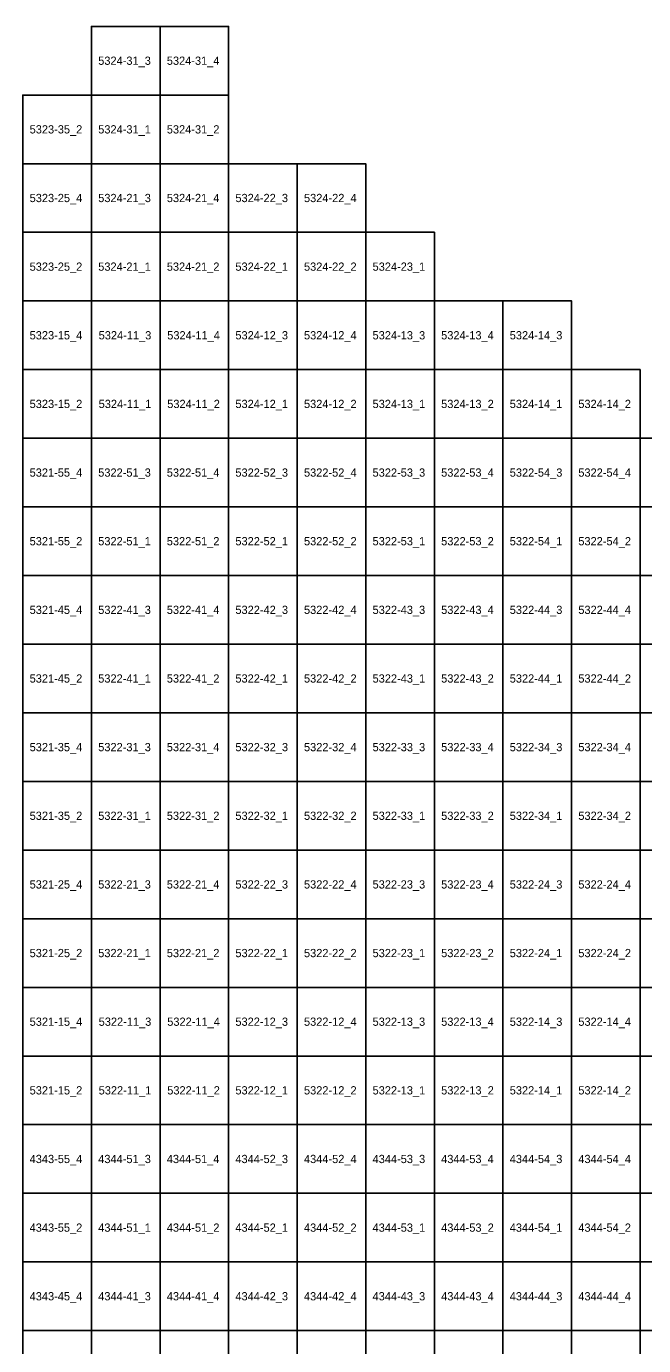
# Model space of a CAD drawing. Extents: x 312500 to 765000, y 172500 to 440000.
# Drawn here: x 572629 to 595129, y 391952 to 440000 of the extents above; entities that cross this region are included whole.
import ezdxf

# ---------------------------------------------------------------- set-up
doc = ezdxf.new("R2010")
doc.units = 0
doc.layers.add('Topo5_ramis_TKS2025', color=7, linetype='Continuous')
doc.layers.add('Topo5_ramis_TKS2025_Nr', color=7, linetype='Continuous')

msp = doc.modelspace()

# ---------------------------------------------------------------- linework, layer by layer
at = {"layer": 'Topo5_ramis_TKS2025'}
for points in [[(575000, 437500), (575000, 440000), (577500, 440000), (577500, 437500), (575000, 437500)], [(577500, 437500), (577500, 440000), (580000, 440000), (580000, 437500), (577500, 437500)], [(572500, 435000), (572500, 437500), (575000, 437500), (575000, 435000), (572500, 435000)], [(575000, 435000), (575000, 437500), (577500, 437500), (577500, 435000), (575000, 435000)], [(577500, 435000), (577500, 437500), (580000, 437500), (580000, 435000), (577500, 435000)], [(572500, 432500), (572500, 435000), (575000, 435000), (575000, 432500), (572500, 432500)], [(575000, 432500), (575000, 435000), (577500, 435000), (577500, 432500), (575000, 432500)], [(577500, 432500), (577500, 435000), (580000, 435000), (580000, 432500), (577500, 432500)], [(580000, 432500), (580000, 435000), (582500, 435000), (582500, 432500), (580000, 432500)], [(582500, 432500), (582500, 435000), (585000, 435000), (585000, 432500), (582500, 432500)], [(572500, 430000), (572500, 432500), (575000, 432500), (575000, 430000), (572500, 430000)], [(575000, 430000), (575000, 432500), (577500, 432500), (577500, 430000), (575000, 430000)], [(577500, 430000), (577500, 432500), (580000, 432500), (580000, 430000), (577500, 430000)], [(580000, 430000), (580000, 432500), (582500, 432500), (582500, 430000), (580000, 430000)], [(582500, 430000), (582500, 432500), (585000, 432500), (585000, 430000), (582500, 430000)], [(585000, 430000), (585000, 432500), (587500, 432500), (587500, 430000), (585000, 430000)], [(572500, 427500), (572500, 430000), (575000, 430000), (575000, 427500), (572500, 427500)], [(575000, 427500), (575000, 430000), (577500, 430000), (577500, 427500), (575000, 427500)], [(577500, 427500), (577500, 430000), (580000, 430000), (580000, 427500), (577500, 427500)], [(580000, 427500), (580000, 430000), (582500, 430000), (582500, 427500), (580000, 427500)], [(582500, 427500), (582500, 430000), (585000, 430000), (585000, 427500), (582500, 427500)], [(585000, 427500), (585000, 430000), (587500, 430000), (587500, 427500), (585000, 427500)], [(587500, 427500), (587500, 430000), (590000, 430000), (590000, 427500), (587500, 427500)], [(590000, 427500), (590000, 430000), (592500, 430000), (592500, 427500), (590000, 427500)], [(572500, 425000), (572500, 427500), (575000, 427500), (575000, 425000), (572500, 425000)], [(575000, 425000), (575000, 427500), (577500, 427500), (577500, 425000), (575000, 425000)], [(577500, 425000), (577500, 427500), (580000, 427500), (580000, 425000), (577500, 425000)], [(580000, 425000), (580000, 427500), (582500, 427500), (582500, 425000), (580000, 425000)], [(582500, 425000), (582500, 427500), (585000, 427500), (585000, 425000), (582500, 425000)], [(585000, 425000), (585000, 427500), (587500, 427500), (587500, 425000), (585000, 425000)], [(587500, 425000), (587500, 427500), (590000, 427500), (590000, 425000), (587500, 425000)], [(590000, 425000), (590000, 427500), (592500, 427500), (592500, 425000), (590000, 425000)], [(592500, 425000), (592500, 427500), (595000, 427500), (595000, 425000), (592500, 425000)], [(572500, 422500), (572500, 425000), (575000, 425000), (575000, 422500), (572500, 422500)], [(575000, 422500), (575000, 425000), (577500, 425000), (577500, 422500), (575000, 422500)], [(577500, 422500), (577500, 425000), (580000, 425000), (580000, 422500), (577500, 422500)], [(580000, 422500), (580000, 425000), (582500, 425000), (582500, 422500), (580000, 422500)], [(582500, 422500), (582500, 425000), (585000, 425000), (585000, 422500), (582500, 422500)], [(585000, 422500), (585000, 425000), (587500, 425000), (587500, 422500), (585000, 422500)], [(587500, 422500), (587500, 425000), (590000, 425000), (590000, 422500), (587500, 422500)], [(590000, 422500), (590000, 425000), (592500, 425000), (592500, 422500), (590000, 422500)], [(592500, 422500), (592500, 425000), (595000, 425000), (595000, 422500), (592500, 422500)], [(595000, 422500), (595000, 425000), (597500, 425000), (597500, 422500), (595000, 422500)], [(572500, 420000), (572500, 422500), (575000, 422500), (575000, 420000), (572500, 420000)], [(575000, 420000), (575000, 422500), (577500, 422500), (577500, 420000), (575000, 420000)], [(577500, 420000), (577500, 422500), (580000, 422500), (580000, 420000), (577500, 420000)], [(580000, 420000), (580000, 422500), (582500, 422500), (582500, 420000), (580000, 420000)], [(582500, 420000), (582500, 422500), (585000, 422500), (585000, 420000), (582500, 420000)], [(585000, 420000), (585000, 422500), (587500, 422500), (587500, 420000), (585000, 420000)], [(587500, 420000), (587500, 422500), (590000, 422500), (590000, 420000), (587500, 420000)], [(590000, 420000), (590000, 422500), (592500, 422500), (592500, 420000), (590000, 420000)], [(592500, 420000), (592500, 422500), (595000, 422500), (595000, 420000), (592500, 420000)], [(595000, 420000), (595000, 422500), (597500, 422500), (597500, 420000), (595000, 420000)], [(572500, 417500), (572500, 420000), (575000, 420000), (575000, 417500), (572500, 417500)], [(575000, 417500), (575000, 420000), (577500, 420000), (577500, 417500), (575000, 417500)], [(577500, 417500), (577500, 420000), (580000, 420000), (580000, 417500), (577500, 417500)], [(580000, 417500), (580000, 420000), (582500, 420000), (582500, 417500), (580000, 417500)], [(582500, 417500), (582500, 420000), (585000, 420000), (585000, 417500), (582500, 417500)], [(585000, 417500), (585000, 420000), (587500, 420000), (587500, 417500), (585000, 417500)], [(587500, 417500), (587500, 420000), (590000, 420000), (590000, 417500), (587500, 417500)], [(590000, 417500), (590000, 420000), (592500, 420000), (592500, 417500), (590000, 417500)], [(592500, 417500), (592500, 420000), (595000, 420000), (595000, 417500), (592500, 417500)], [(595000, 417500), (595000, 420000), (597500, 420000), (597500, 417500), (595000, 417500)], [(572500, 415000), (572500, 417500), (575000, 417500), (575000, 415000), (572500, 415000)], [(575000, 415000), (575000, 417500), (577500, 417500), (577500, 415000), (575000, 415000)], [(577500, 415000), (577500, 417500), (580000, 417500), (580000, 415000), (577500, 415000)], [(580000, 415000), (580000, 417500), (582500, 417500), (582500, 415000), (580000, 415000)], [(582500, 415000), (582500, 417500), (585000, 417500), (585000, 415000), (582500, 415000)], [(585000, 415000), (585000, 417500), (587500, 417500), (587500, 415000), (585000, 415000)], [(587500, 415000), (587500, 417500), (590000, 417500), (590000, 415000), (587500, 415000)], [(590000, 415000), (590000, 417500), (592500, 417500), (592500, 415000), (590000, 415000)], [(592500, 415000), (592500, 417500), (595000, 417500), (595000, 415000), (592500, 415000)], [(595000, 415000), (595000, 417500), (597500, 417500), (597500, 415000), (595000, 415000)], [(572500, 412500), (572500, 415000), (575000, 415000), (575000, 412500), (572500, 412500)], [(575000, 412500), (575000, 415000), (577500, 415000), (577500, 412500), (575000, 412500)], [(577500, 412500), (577500, 415000), (580000, 415000), (580000, 412500), (577500, 412500)], [(580000, 412500), (580000, 415000), (582500, 415000), (582500, 412500), (580000, 412500)], [(582500, 412500), (582500, 415000), (585000, 415000), (585000, 412500), (582500, 412500)], [(585000, 412500), (585000, 415000), (587500, 415000), (587500, 412500), (585000, 412500)], [(587500, 412500), (587500, 415000), (590000, 415000), (590000, 412500), (587500, 412500)], [(590000, 412500), (590000, 415000), (592500, 415000), (592500, 412500), (590000, 412500)], [(592500, 412500), (592500, 415000), (595000, 415000), (595000, 412500), (592500, 412500)], [(595000, 412500), (595000, 415000), (597500, 415000), (597500, 412500), (595000, 412500)], [(572500, 410000), (572500, 412500), (575000, 412500), (575000, 410000), (572500, 410000)], [(575000, 410000), (575000, 412500), (577500, 412500), (577500, 410000), (575000, 410000)], [(577500, 410000), (577500, 412500), (580000, 412500), (580000, 410000), (577500, 410000)], [(580000, 410000), (580000, 412500), (582500, 412500), (582500, 410000), (580000, 410000)], [(582500, 410000), (582500, 412500), (585000, 412500), (585000, 410000), (582500, 410000)], [(585000, 410000), (585000, 412500), (587500, 412500), (587500, 410000), (585000, 410000)], [(587500, 410000), (587500, 412500), (590000, 412500), (590000, 410000), (587500, 410000)], [(590000, 410000), (590000, 412500), (592500, 412500), (592500, 410000), (590000, 410000)], [(592500, 410000), (592500, 412500), (595000, 412500), (595000, 410000), (592500, 410000)], [(595000, 410000), (595000, 412500), (597500, 412500), (597500, 410000), (595000, 410000)], [(572500, 407500), (572500, 410000), (575000, 410000), (575000, 407500), (572500, 407500)], [(575000, 407500), (575000, 410000), (577500, 410000), (577500, 407500), (575000, 407500)], [(577500, 407500), (577500, 410000), (580000, 410000), (580000, 407500), (577500, 407500)], [(580000, 407500), (580000, 410000), (582500, 410000), (582500, 407500), (580000, 407500)], [(582500, 407500), (582500, 410000), (585000, 410000), (585000, 407500), (582500, 407500)], [(585000, 407500), (585000, 410000), (587500, 410000), (587500, 407500), (585000, 407500)], [(587500, 407500), (587500, 410000), (590000, 410000), (590000, 407500), (587500, 407500)], [(590000, 407500), (590000, 410000), (592500, 410000), (592500, 407500), (590000, 407500)], [(592500, 407500), (592500, 410000), (595000, 410000), (595000, 407500), (592500, 407500)], [(595000, 407500), (595000, 410000), (597500, 410000), (597500, 407500), (595000, 407500)], [(572500, 405000), (572500, 407500), (575000, 407500), (575000, 405000), (572500, 405000)], [(575000, 405000), (575000, 407500), (577500, 407500), (577500, 405000), (575000, 405000)], [(577500, 405000), (577500, 407500), (580000, 407500), (580000, 405000), (577500, 405000)], [(580000, 405000), (580000, 407500), (582500, 407500), (582500, 405000), (580000, 405000)], [(582500, 405000), (582500, 407500), (585000, 407500), (585000, 405000), (582500, 405000)], [(585000, 405000), (585000, 407500), (587500, 407500), (587500, 405000), (585000, 405000)], [(587500, 405000), (587500, 407500), (590000, 407500), (590000, 405000), (587500, 405000)], [(590000, 405000), (590000, 407500), (592500, 407500), (592500, 405000), (590000, 405000)], [(592500, 405000), (592500, 407500), (595000, 407500), (595000, 405000), (592500, 405000)], [(595000, 405000), (595000, 407500), (597500, 407500), (597500, 405000), (595000, 405000)], [(572500, 402500), (572500, 405000), (575000, 405000), (575000, 402500), (572500, 402500)], [(575000, 402500), (575000, 405000), (577500, 405000), (577500, 402500), (575000, 402500)], [(577500, 402500), (577500, 405000), (580000, 405000), (580000, 402500), (577500, 402500)], [(580000, 402500), (580000, 405000), (582500, 405000), (582500, 402500), (580000, 402500)], [(582500, 402500), (582500, 405000), (585000, 405000), (585000, 402500), (582500, 402500)], [(585000, 402500), (585000, 405000), (587500, 405000), (587500, 402500), (585000, 402500)], [(587500, 402500), (587500, 405000), (590000, 405000), (590000, 402500), (587500, 402500)], [(590000, 402500), (590000, 405000), (592500, 405000), (592500, 402500), (590000, 402500)], [(592500, 402500), (592500, 405000), (595000, 405000), (595000, 402500), (592500, 402500)], [(595000, 402500), (595000, 405000), (597500, 405000), (597500, 402500), (595000, 402500)], [(572500, 400000), (572500, 402500), (575000, 402500), (575000, 400000), (572500, 400000)], [(575000, 400000), (575000, 402500), (577500, 402500), (577500, 400000), (575000, 400000)], [(577500, 400000), (577500, 402500), (580000, 402500), (580000, 400000), (577500, 400000)], [(580000, 400000), (580000, 402500), (582500, 402500), (582500, 400000), (580000, 400000)], [(582500, 400000), (582500, 402500), (585000, 402500), (585000, 400000), (582500, 400000)], [(585000, 400000), (585000, 402500), (587500, 402500), (587500, 400000), (585000, 400000)], [(587500, 400000), (587500, 402500), (590000, 402500), (590000, 400000), (587500, 400000)], [(590000, 400000), (590000, 402500), (592500, 402500), (592500, 400000), (590000, 400000)], [(592500, 400000), (592500, 402500), (595000, 402500), (595000, 400000), (592500, 400000)], [(595000, 400000), (595000, 402500), (597500, 402500), (597500, 400000), (595000, 400000)], [(572500, 397500), (572500, 400000), (575000, 400000), (575000, 397500), (572500, 397500)], [(575000, 397500), (575000, 400000), (577500, 400000), (577500, 397500), (575000, 397500)], [(577500, 397500), (577500, 400000), (580000, 400000), (580000, 397500), (577500, 397500)], [(580000, 397500), (580000, 400000), (582500, 400000), (582500, 397500), (580000, 397500)], [(582500, 397500), (582500, 400000), (585000, 400000), (585000, 397500), (582500, 397500)], [(585000, 397500), (585000, 400000), (587500, 400000), (587500, 397500), (585000, 397500)], [(587500, 397500), (587500, 400000), (590000, 400000), (590000, 397500), (587500, 397500)], [(590000, 397500), (590000, 400000), (592500, 400000), (592500, 397500), (590000, 397500)], [(592500, 397500), (592500, 400000), (595000, 400000), (595000, 397500), (592500, 397500)], [(595000, 397500), (595000, 400000), (597500, 400000), (597500, 397500), (595000, 397500)], [(572500, 395000), (572500, 397500), (575000, 397500), (575000, 395000), (572500, 395000)], [(575000, 395000), (575000, 397500), (577500, 397500), (577500, 395000), (575000, 395000)], [(577500, 395000), (577500, 397500), (580000, 397500), (580000, 395000), (577500, 395000)], [(580000, 395000), (580000, 397500), (582500, 397500), (582500, 395000), (580000, 395000)], [(582500, 395000), (582500, 397500), (585000, 397500), (585000, 395000), (582500, 395000)], [(585000, 395000), (585000, 397500), (587500, 397500), (587500, 395000), (585000, 395000)], [(587500, 395000), (587500, 397500), (590000, 397500), (590000, 395000), (587500, 395000)], [(590000, 395000), (590000, 397500), (592500, 397500), (592500, 395000), (590000, 395000)], [(592500, 395000), (592500, 397500), (595000, 397500), (595000, 395000), (592500, 395000)], [(595000, 395000), (595000, 397500), (597500, 397500), (597500, 395000), (595000, 395000)], [(572500, 392500), (572500, 395000), (575000, 395000), (575000, 392500), (572500, 392500)], [(575000, 392500), (575000, 395000), (577500, 395000), (577500, 392500), (575000, 392500)], [(577500, 392500), (577500, 395000), (580000, 395000), (580000, 392500), (577500, 392500)], [(580000, 392500), (580000, 395000), (582500, 395000), (582500, 392500), (580000, 392500)], [(582500, 392500), (582500, 395000), (585000, 395000), (585000, 392500), (582500, 392500)], [(585000, 392500), (585000, 395000), (587500, 395000), (587500, 392500), (585000, 392500)], [(587500, 392500), (587500, 395000), (590000, 395000), (590000, 392500), (587500, 392500)], [(590000, 392500), (590000, 395000), (592500, 395000), (592500, 392500), (590000, 392500)], [(592500, 392500), (592500, 395000), (595000, 395000), (595000, 392500), (592500, 392500)], [(595000, 392500), (595000, 395000), (597500, 395000), (597500, 392500), (595000, 392500)], [(572500, 390000), (572500, 392500), (575000, 392500), (575000, 390000), (572500, 390000)], [(575000, 390000), (575000, 392500), (577500, 392500), (577500, 390000), (575000, 390000)], [(577500, 390000), (577500, 392500), (580000, 392500), (580000, 390000), (577500, 390000)], [(580000, 390000), (580000, 392500), (582500, 392500), (582500, 390000), (580000, 390000)], [(582500, 390000), (582500, 392500), (585000, 392500), (585000, 390000), (582500, 390000)], [(585000, 390000), (585000, 392500), (587500, 392500), (587500, 390000), (585000, 390000)], [(587500, 390000), (587500, 392500), (590000, 392500), (590000, 390000), (587500, 390000)], [(590000, 390000), (590000, 392500), (592500, 392500), (592500, 390000), (590000, 390000)], [(592500, 390000), (592500, 392500), (595000, 392500), (595000, 390000), (592500, 390000)], [(595000, 390000), (595000, 392500), (597500, 392500), (597500, 390000), (595000, 390000)]]:
    msp.add_lwpolyline(points, dxfattribs=at)

# ---------------------------------------------------------------- texts
at = {"layer": 'Topo5_ramis_TKS2025_Nr'}
for s, p in [('5324-31_3', (575248, 438600)), ('5324-31_4', (577748, 438600)), ('5323-35_2', (572748, 436100)), ('5324-31_1', (575248, 436100)), ('5324-31_2', (577748, 436100)), ('5323-25_4', (572748, 433600)), ('5324-21_3', (575248, 433600)), ('5324-21_4', (577748, 433600)), ('5324-22_3', (580248, 433600)), ('5324-22_4', (582748, 433600)), ('5323-25_2', (572748, 431100)), ('5324-21_1', (575248, 431100)), ('5324-21_2', (577748, 431100)), ('5324-22_1', (580248, 431100)), ('5324-22_2', (582748, 431100)), ('5324-23_1', (585248, 431100)), ('5323-15_4', (572748, 428600)), ('5324-11_3', (575264, 428600)), ('5324-11_4', (577764, 428600)), ('5324-12_3', (580248, 428600)), ('5324-12_4', (582748, 428600)), ('5324-13_3', (585248, 428600)), ('5324-13_4', (587748, 428600)), ('5324-14_3', (590248, 428600)), ('5323-15_2', (572748, 426100)), ('5324-11_1', (575264, 426100)), ('5324-11_2', (577764, 426100)), ('5324-12_1', (580248, 426100)), ('5324-12_2', (582748, 426100)), ('5324-13_1', (585248, 426100)), ('5324-13_2', (587748, 426100)), ('5324-14_1', (590248, 426100)), ('5324-14_2', (592748, 426100)), ('5321-55_4', (572748, 423600)), ('5322-51_3', (575248, 423600)), ('5322-51_4', (577748, 423600)), ('5322-52_3', (580248, 423600)), ('5322-52_4', (582748, 423600)), ('5322-53_3', (585248, 423600)), ('5322-53_4', (587748, 423600)), ('5322-54_3', (590248, 423600)), ('5322-54_4', (592748, 423600)), ('5321-55_2', (572748, 421100)), ('5322-51_1', (575248, 421100)), ('5322-51_2', (577748, 421100)), ('5322-52_1', (580248, 421100)), ('5322-52_2', (582748, 421100)), ('5322-53_1', (585248, 421100)), ('5322-53_2', (587748, 421100)), ('5322-54_1', (590248, 421100)), ('5322-54_2', (592748, 421100)), ('5321-45_4', (572748, 418600)), ('5322-41_3', (575248, 418600)), ('5322-41_4', (577748, 418600)), ('5322-42_3', (580248, 418600)), ('5322-42_4', (582748, 418600)), ('5322-43_3', (585248, 418600)), ('5322-43_4', (587748, 418600)), ('5322-44_3', (590248, 418600)), ('5322-44_4', (592748, 418600)), ('5321-45_2', (572748, 416100)), ('5322-41_1', (575248, 416100)), ('5322-41_2', (577748, 416100)), ('5322-42_1', (580248, 416100)), ('5322-42_2', (582748, 416100)), ('5322-43_1', (585248, 416100)), ('5322-43_2', (587748, 416100)), ('5322-44_1', (590248, 416100)), ('5322-44_2', (592748, 416100)), ('5321-35_4', (572748, 413600)), ('5322-31_3', (575248, 413600)), ('5322-31_4', (577748, 413600)), ('5322-32_3', (580248, 413600)), ('5322-32_4', (582748, 413600)), ('5322-33_3', (585248, 413600)), ('5322-33_4', (587748, 413600)), ('5322-34_3', (590248, 413600)), ('5322-34_4', (592748, 413600)), ('5321-35_2', (572748, 411100)), ('5322-31_1', (575248, 411100)), ('5322-31_2', (577748, 411100)), ('5322-32_1', (580248, 411100)), ('5322-32_2', (582748, 411100)), ('5322-33_1', (585248, 411100)), ('5322-33_2', (587748, 411100)), ('5322-34_1', (590248, 411100)), ('5322-34_2', (592748, 411100)), ('5321-25_4', (572748, 408600)), ('5322-21_3', (575248, 408600)), ('5322-21_4', (577748, 408600)), ('5322-22_3', (580248, 408600)), ('5322-22_4', (582748, 408600)), ('5322-23_3', (585248, 408600)), ('5322-23_4', (587748, 408600)), ('5322-24_3', (590248, 408600)), ('5322-24_4', (592748, 408600)), ('5321-25_2', (572748, 406100)), ('5322-21_1', (575248, 406100)), ('5322-21_2', (577748, 406100)), ('5322-22_1', (580248, 406100)), ('5322-22_2', (582748, 406100)), ('5322-23_1', (585248, 406100)), ('5322-23_2', (587748, 406100)), ('5322-24_1', (590248, 406100)), ('5322-24_2', (592748, 406100)), ('5321-15_4', (572748, 403600)), ('5322-11_3', (575264, 403600)), ('5322-11_4', (577764, 403600)), ('5322-12_3', (580248, 403600)), ('5322-12_4', (582748, 403600)), ('5322-13_3', (585248, 403600)), ('5322-13_4', (587748, 403600)), ('5322-14_3', (590248, 403600)), ('5322-14_4', (592748, 403600)), ('5321-15_2', (572748, 401100)), ('5322-11_1', (575264, 401100)), ('5322-11_2', (577764, 401100)), ('5322-12_1', (580248, 401100)), ('5322-12_2', (582748, 401100)), ('5322-13_1', (585248, 401100)), ('5322-13_2', (587748, 401100)), ('5322-14_1', (590248, 401100)), ('5322-14_2', (592748, 401100)), ('4343-55_4', (572748, 398600)), ('4344-51_3', (575248, 398600)), ('4344-51_4', (577748, 398600)), ('4344-52_3', (580248, 398600)), ('4344-52_4', (582748, 398600)), ('4344-53_3', (585248, 398600)), ('4344-53_4', (587748, 398600)), ('4344-54_3', (590248, 398600)), ('4344-54_4', (592748, 398600)), ('4343-55_2', (572748, 396100)), ('4344-51_1', (575248, 396100)), ('4344-51_2', (577748, 396100)), ('4344-52_1', (580248, 396100)), ('4344-52_2', (582748, 396100)), ('4344-53_1', (585248, 396100)), ('4344-53_2', (587748, 396100)), ('4344-54_1', (590248, 396100)), ('4344-54_2', (592748, 396100)), ('4343-45_4', (572748, 393600)), ('4344-41_3', (575248, 393600)), ('4344-41_4', (577748, 393600)), ('4344-42_3', (580248, 393600)), ('4344-42_4', (582748, 393600)), ('4344-43_3', (585248, 393600)), ('4344-43_4', (587748, 393600)), ('4344-44_3', (590248, 393600)), ('4344-44_4', (592748, 393600))]:
    msp.add_text(s, height=300, dxfattribs=at).set_placement(p)

doc.saveas('drawing.dxf')
